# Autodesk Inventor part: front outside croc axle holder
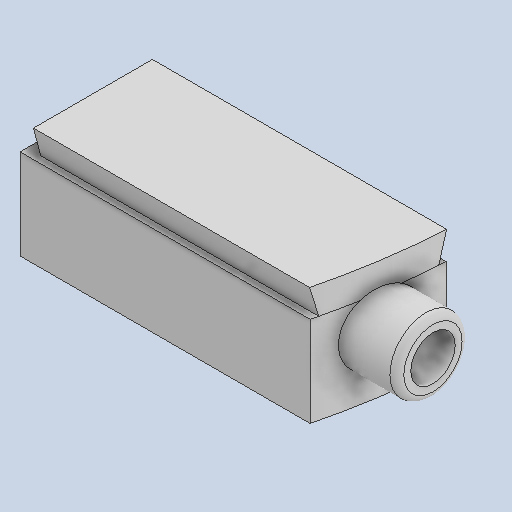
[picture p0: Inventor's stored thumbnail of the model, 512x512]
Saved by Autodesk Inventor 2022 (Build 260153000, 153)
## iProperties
Created: 2021-07
Part Number: front outside croc axle holder
Material: Generic
Document SubType Name: Modeling
Designer: garre
Density: 1 g/cm^3
Appearance: Default
Author: garre
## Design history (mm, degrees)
derived "croc skate axle holders.ipt"
feature "front outside::croc skate axle holders.ipt" dims "d0" = 10
tag "TaggingFeature1"
body "Solid1"
